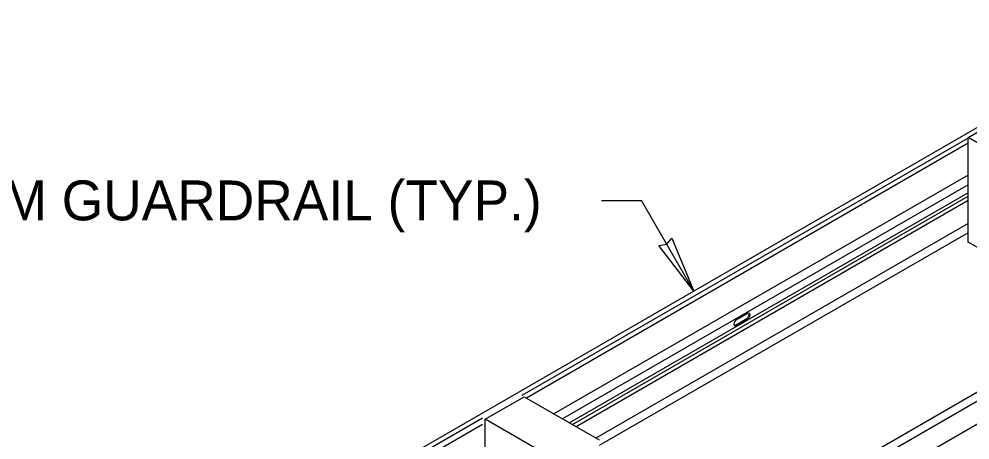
# Model space of a CAD drawing. Extents: x 99862 to 103680, y 99470 to 102076.
# Drawn here: x 101379.6 to 101761.2, y 100559 to 100728.1 of the extents above; entities that cross this region are included whole.
import ezdxf

# ---------------------------------------------------------------- set-up
doc = ezdxf.new("R2010")
doc.units = 0
for name, color, linetype in [('Level 15', 7, 'Continuous'), ('Level 2', 7, 'Continuous'), ('Level 20', 7, 'Continuous'), ('Level 27', 7, 'Continuous'), ('Level 5', 7, 'Continuous')]:
    doc.layers.add(name, color=color, linetype=linetype)

msp = doc.modelspace()

# ---------------------------------------------------------------- linework, layer by layer
at = {"layer": 'Level 15'}
for p in [(101613.4, 100655.22), (101650.42, 100618.81)]:
    msp.add_line(p, (101629.4, 100655.22), dxfattribs=at)
msp.add_lwpolyline([(101650.42, 100618.81), (101636.42, 100637.09), (101639.53, 100637.67), (101641.59, 100640.08)], close=True, dxfattribs=at)
at = {"layer": 'Level 2'}
for p, q in [((101760.5, 100680.5), (101776.08, 100689.5)), ((101760.5, 100638.5), (101760.5, 100680.5)), ((101791.67, 100662.5), (101760.5, 100680.5)), ((101791.67, 100620.5), (101760.5, 100638.5)), ((101566.72, 100567.38), (101582.31, 100576.38)), ((101582.31, 100576.38), (101612.41, 100559)), ((101566.72, 100525.38), (101566.72, 100567.38)), ((101596.82, 100550), (101566.72, 100567.38))]:
    msp.add_line(p, q, dxfattribs=at)
at = {"layer": 'Level 27'}
for p, q in [((101839.68, 100728.08), (101483.32, 100522.34)), ((101972.86, 100698.69), (101550.67, 100454.94)), ((101975.49, 100696.61), (101553.24, 100452.83)), ((101980.28, 100690.17), (101558.01, 100446.38)), ((101760.5, 100680.23), (101581.46, 100576.86)), ((101760.5, 100678.15), (101583.26, 100575.83)), ((101760.5, 100665.42), (101594.29, 100569.46)), ((101760.5, 100661.45), (101597.73, 100567.47)), ((101760.5, 100658.21), (101600.53, 100565.85)), ((101601.67, 100565.2), (101760.5, 100656.89)), ((101760.5, 100655.15), (101603.18, 100564.32)), ((101760.5, 100645.95), (101611.15, 100559.72)), ((101760.5, 100642.25), (101612.41, 100556.75)), ((101667.12, 100605.17), (101671.67, 100607.79)), ((101667.45, 100607.23), (101671.99, 100609.86)), ((101671.99, 100607.61), (101667.45, 100604.98)), ((101565.64, 100567.73), (101456.33, 100504.61)), ((101565.64, 100565.22), (101491.05, 100522.15))]:
    msp.add_line(p, q, dxfattribs=at)
for centre, ratio, start_param, end_param in [((101671.99, 100608.73), 0.577351, 3.92699, 7.068583), ((101667.45, 100606.11), 0.577351, 0.785398, 3.92699), ((101671.67, 100608.92), 0.57735, 3.926991, 5.544485), ((101667.12, 100606.29), 0.57735, 3.379534, 3.926991)]:
    msp.add_ellipse(centre, major_axis=(0.69, 1.19), ratio=ratio, start_param=start_param, end_param=end_param, dxfattribs=at)
at = {"layer": 'Level 5'}
for p, q in [((101667.45, 100607.23), (101667.45, 100607.23)), ((101671.99, 100609.86), (101671.99, 100609.86))]:
    msp.add_line(p, q, dxfattribs=at)

# ---------------------------------------------------------------- texts
at = {"layer": 'Level 20'}
msp.add_text('W-BEAM GUARDRAIL (TYP.)', height=16, dxfattribs=at).set_placement((101302.87, 100647.22))

doc.saveas('drawing.dxf')
